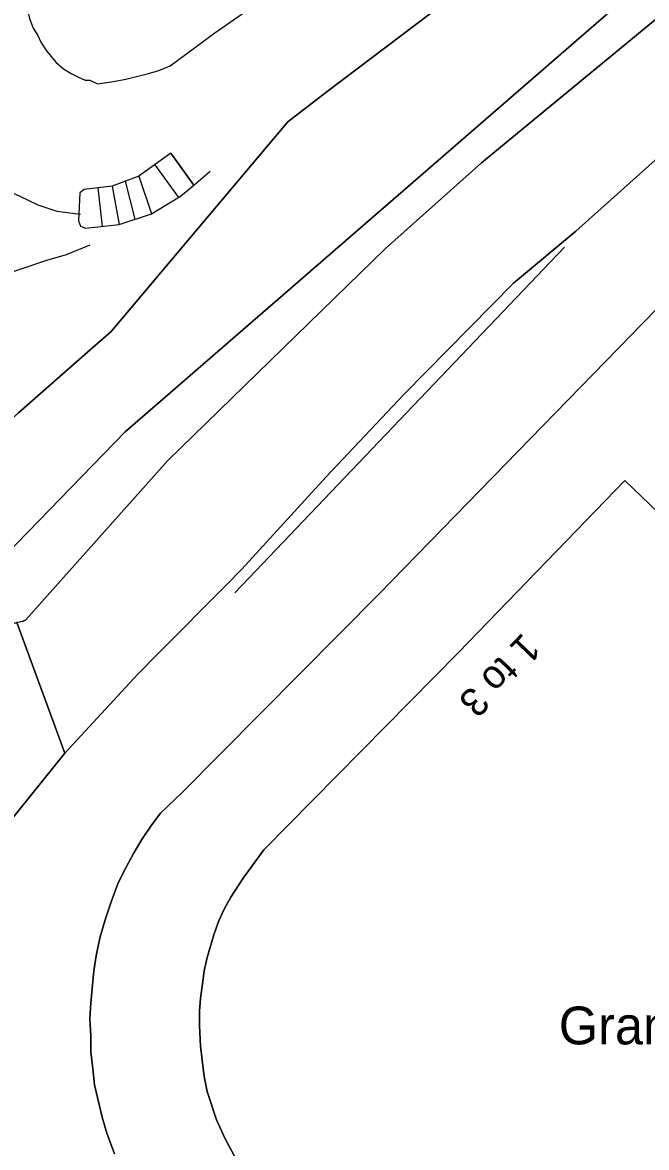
# Model space of a CAD drawing. Extents: x 529240 to 530363, y 179600 to 180767.
# Drawn here: x 530085.5 to 530118.5, y 180396.1 to 180455.7 of the extents above; entities that cross this region are included whole.
import ezdxf

# ---------------------------------------------------------------- set-up
doc = ezdxf.new("R2010")
doc.units = 0
for name, color, linetype in [('Building', 7, 'Continuous'), ('General surface', 7, 'Continuous'), ('Road Or Track', 7, 'Continuous'), ('Roadside', 7, 'Continuous'), ('Unclassified', 7, 'Continuous')]:
    doc.layers.add(name, color=color, linetype=linetype)

msp = doc.modelspace()

# ---------------------------------------------------------------- linework, layer by layer
at = {"layer": 'Building'}
for points in [[(530085.7, 180456.85), (530085.7, 180456.6), (530085.85, 180455.9), (530086.05, 180455.4), (530086.3, 180455), (530086.45, 180454.65), (530086.75, 180454.2), (530087.25, 180453.6), (530087.65, 180453.25), (530088.05, 180453), (530088.45, 180452.8), (530088.8, 180452.65), (530089.05, 180452.65), (530089.45, 180452.45), (530090.2, 180452.55), (530090.95, 180452.7), (530092.15, 180453), (530092.7, 180453.15), (530093.3, 180453.4), (530095.65, 180455.15), (530105.2, 180461.8)], [(530085.85, 180455.9), (530086.05, 180455.4), (530086.3, 180455), (530086.45, 180454.65), (530086.75, 180454.2), (530087.25, 180453.6), (530087.65, 180453.25), (530088.05, 180453), (530088.45, 180452.8), (530088.8, 180452.65), (530089.05, 180452.65), (530089.45, 180452.45), (530090.2, 180452.55), (530090.95, 180452.7), (530092.15, 180453), (530092.7, 180453.15), (530093.3, 180453.4), (530095.65, 180455.15), (530105.2, 180461.8)], [(530119, 180440.5), (530104.35, 180425.45), (530093.9, 180414.9), (530092.8, 180413.85), (530092.3, 180413.2), (530091.8, 180412.45), (530091.35, 180411.7), (530090.95, 180410.95), (530090.55, 180410.15), (530090.15, 180409.1), (530089.85, 180408.2), (530089.6, 180407.3), (530089.4, 180406.4), (530089.25, 180405.5), (530089.1, 180403.8), (530089.05, 180402.95), (530089.1, 180402.05), (530089.1, 180401.2), (530089.2, 180400.3), (530089.3, 180399.45), (530089.7, 180397.75), (530089.95, 180396.9), (530090.35, 180395.8)], [(530119, 180440.5), (530104.35, 180425.45), (530093.9, 180414.9), (530092.8, 180413.85), (530092.3, 180413.2), (530091.8, 180412.45), (530091.35, 180411.7), (530090.95, 180410.95), (530090.55, 180410.15), (530090.15, 180409.1), (530089.85, 180408.2), (530089.6, 180407.3), (530089.4, 180406.4), (530089.25, 180405.5), (530089.1, 180403.8), (530089.05, 180402.95), (530089.1, 180402.05), (530089.1, 180401.2), (530089.2, 180400.3), (530089.3, 180399.45), (530089.7, 180397.75), (530089.95, 180396.9), (530090.35, 180395.8)], [(530155.45, 180405.1), (530126.8, 180433.1), (530121.3, 180427.65), (530117.35, 180431.45), (530108.55, 180422.35), (530098.25, 180411.9), (530097.15, 180410.4), (530096.5, 180409.4), (530096.15, 180408.75), (530095.85, 180408.1), (530095.6, 180407.4), (530095.25, 180406.2), (530095.1, 180405.5), (530095, 180404.8), (530094.9, 180404.05), (530094.85, 180403.35), (530094.85, 180402.6), (530094.9, 180401.5), (530095.1, 180399.9), (530095.25, 180399.1), (530095.75, 180397.6), (530096.2, 180396.6), (530096.9, 180395.3)], [(530096.9, 180395.3), (530096.2, 180396.6), (530095.75, 180397.6), (530095.25, 180399.1), (530095.1, 180399.9), (530094.9, 180401.5), (530094.85, 180402.6), (530094.85, 180403.35), (530094.9, 180404.05), (530095, 180404.8), (530095.1, 180405.5), (530095.25, 180406.2), (530095.6, 180407.4), (530095.85, 180408.1), (530096.15, 180408.75), (530096.5, 180409.4), (530097.15, 180410.4), (530098.25, 180411.9), (530108.55, 180422.35), (530117.35, 180431.45), (530121.3, 180427.65), (530126.8, 180433.1)], [(530096.9, 180395.3), (530096.2, 180396.6), (530095.75, 180397.6), (530095.25, 180399.1), (530095.1, 180399.9), (530094.9, 180401.5), (530094.85, 180402.6), (530094.85, 180403.35), (530094.9, 180404.05), (530095, 180404.8), (530095.1, 180405.5), (530095.25, 180406.2), (530095.6, 180407.4), (530095.85, 180408.1), (530096.15, 180408.75), (530096.5, 180409.4), (530097.15, 180410.4), (530098.25, 180411.9), (530108.55, 180422.35), (530117.35, 180431.45), (530121.3, 180427.65)]]:
    msp.add_lwpolyline(points, dxfattribs=at)
at = {"layer": 'General surface'}
msp.add_lwpolyline([(530094.54, 180447.09), (530093.33, 180448.78), (530091.63, 180447.56), (530090.23, 180447.03), (530088.74, 180446.86), (530088.51, 180446.68), (530088.44, 180445.19), (530088.55, 180444.92), (530088.81, 180444.8), (530090.6, 180445), (530092.3, 180445.57), (530093.84, 180446.5)], close=True, dxfattribs=at)
for points in [[(530093.33, 180448.78), (530094.54, 180447.09)], [(530092.48, 180448.17), (530093.73, 180446.43)], [(530091.45, 180445.28), (530090.93, 180447.3)], [(530091.63, 180447.56), (530092.3, 180445.57)], [(530089.71, 180444.9), (530089.48, 180446.94)], [(530090.23, 180447.03), (530090.6, 180445)]]:
    msp.add_lwpolyline(points, dxfattribs=at)
at = {"layer": 'Road Or Track'}
for points in [[(530083.71, 180426.65), (530083.76, 180426.7), (530083.81, 180426.75), (530083.86, 180426.8), (530083.91, 180426.84), (530083.96, 180426.89), (530084.02, 180426.93), (530090.91, 180434.02), (530103.62, 180445.06), (530118.34, 180457.85), (530120.09, 180459.31), (530146.35, 180481.2), (530151.51, 180485.78), (530157.33, 180491.64), (530165.15, 180500), (530166.31, 180501.24)], [(530168.55, 180499.29), (530168.43, 180498.73), (530158.53, 180489.31), (530154.01, 180485.26), (530126.57, 180462.42), (530126.03, 180462.58), (530125.18, 180461.87), (530125.27, 180461.71), (530125.12, 180461.17), (530121.3, 180457.85), (530119.86, 180456.6), (530109.76, 180448.27), (530104.69, 180443.73), (530093.17, 180432.51), (530088.24, 180426.97), (530085.64, 180424.05), (530085.52, 180424), (530085.46, 180423.98), (530085.39, 180423.96), (530085.32, 180423.95), (530085.25, 180423.94), (530085.18, 180423.93)], [(530143.57, 180487.15), (530143.24, 180486.84), (530129.75, 180474.3), (530127.05, 180471.9), (530126.1, 180471.25), (530121.6, 180467.65), (530119.3, 180465.8), (530117.65, 180464.55), (530115.95, 180463.2), (530112.95, 180460.85), (530110.95, 180459.3), (530107.15, 180456.25), (530101.6, 180452.05)], [(530107.15, 180456.25), (530101.6, 180452.05), (530099.52, 180450.44), (530090.17, 180439.34), (530089.07, 180438.37), (530085.28, 180435.03), (530083.69, 180433.62), (530083.1, 180433.59), (530083.71, 180426.65), (530083.76, 180426.7), (530083.81, 180426.75), (530083.86, 180426.8), (530083.91, 180426.84), (530083.96, 180426.89), (530084.02, 180426.93), (530090.91, 180434.02), (530103.62, 180445.06), (530118.34, 180457.85)], [(530119.86, 180456.6), (530109.76, 180448.27), (530104.69, 180443.73), (530093.17, 180432.51), (530088.24, 180426.97), (530085.64, 180424.05), (530085.52, 180424), (530085.46, 180423.98), (530085.39, 180423.96), (530085.32, 180423.95), (530085.25, 180423.94), (530085.18, 180423.93), (530087.72, 180417.02), (530091.59, 180421.2), (530092.65, 180422.27), (530096.27, 180425.93), (530097.08, 180426.75), (530101.55, 180431.65), (530105.65, 180436), (530111.45, 180441.9), (530114.75, 180444.65), (530118.95, 180448.4)], [(530101.6, 180452.05), (530099.52, 180450.44), (530090.17, 180439.34), (530089.07, 180438.37), (530085.28, 180435.03), (530083.69, 180433.62), (530083.1, 180433.59)], [(530123.65, 180452.3), (530118.95, 180448.4), (530114.75, 180444.65), (530111.45, 180441.9), (530105.65, 180436), (530101.55, 180431.65), (530097.08, 180426.75), (530096.27, 180425.93), (530092.65, 180422.27), (530091.59, 180421.2), (530087.72, 180417.02)], [(530087.72, 180417.02), (530084.15, 180412.58), (530080.91, 180407.89), (530076.79, 180400.63), (530076, 180398.36), (530075.64, 180395.99)]]:
    msp.add_lwpolyline(points, dxfattribs=at)
msp.add_lwpolyline([(530075.45, 180420.08), (530075.54, 180419.53), (530068.51, 180404.42), (530066.03, 180399.09), (530064.72, 180396.29), (530075.64, 180395.99), (530076, 180398.36), (530076.79, 180400.63), (530080.91, 180407.89), (530084.15, 180412.58), (530087.72, 180417.02), (530085.18, 180423.93)], close=True, dxfattribs=at)
at = {"layer": 'Roadside'}
for points in [[(530152.75, 180475.95), (530149.65, 180473.2), (530144.6, 180469), (530140.6, 180465.95), (530132.05, 180458.95), (530129.35, 180456.85), (530124.45, 180452.95), (530123.65, 180452.3), (530118.95, 180448.4), (530114.75, 180444.65), (530111.45, 180441.9), (530105.65, 180436), (530101.55, 180431.65), (530097.08, 180426.75), (530096.27, 180425.93), (530092.65, 180422.27), (530091.59, 180421.2), (530087.72, 180417.02), (530084.15, 180412.58), (530080.91, 180407.89), (530076.79, 180400.63), (530076, 180398.36), (530075.64, 180395.99)], [(530085.85, 180455.9), (530086.05, 180455.4), (530086.3, 180455), (530086.45, 180454.65), (530086.75, 180454.2), (530087.25, 180453.6), (530087.65, 180453.25), (530088.05, 180453), (530088.45, 180452.8), (530088.8, 180452.65), (530089.05, 180452.65), (530089.45, 180452.45), (530090.2, 180452.55), (530090.95, 180452.7), (530092.15, 180453), (530092.7, 180453.15), (530093.3, 180453.4), (530095.65, 180455.15), (530105.2, 180461.8)], [(530118.34, 180457.85), (530103.62, 180445.06), (530090.91, 180434.02), (530084.02, 180426.93)], [(530078.95, 180456.89), (530081.21, 180444.77), (530081.52, 180441.99), (530082.06, 180437.03), (530082.35, 180434.44), (530082.59, 180433.9), (530083.1, 180433.59), (530083.69, 180433.62), (530085.28, 180435.03), (530089.07, 180438.37), (530090.17, 180439.34), (530099.52, 180450.44), (530101.6, 180452.05), (530107.15, 180456.25)], [(530085.46, 180423.98), (530085.52, 180424), (530085.64, 180424.05), (530088.24, 180426.97), (530093.17, 180432.51), (530104.69, 180443.73), (530109.76, 180448.27), (530119.86, 180456.6)], [(530090.35, 180395.8), (530089.95, 180396.9), (530089.7, 180397.75), (530089.3, 180399.45), (530089.2, 180400.3), (530089.1, 180401.2), (530089.1, 180402.05), (530089.05, 180402.95), (530089.1, 180403.8), (530089.25, 180405.5), (530089.4, 180406.4), (530089.6, 180407.3), (530089.85, 180408.2), (530090.15, 180409.1), (530090.55, 180410.15), (530090.95, 180410.95), (530091.35, 180411.7), (530091.8, 180412.45), (530092.3, 180413.2), (530092.8, 180413.85), (530093.9, 180414.9), (530104.35, 180425.45), (530119, 180440.5)]]:
    msp.add_lwpolyline(points, dxfattribs=at)
msp.add_lwpolyline([(530094.54, 180447.09), (530093.33, 180448.78), (530091.63, 180447.56), (530090.23, 180447.03), (530088.74, 180446.86), (530088.51, 180446.68), (530088.44, 180445.19), (530088.55, 180444.92), (530088.81, 180444.8), (530090.6, 180445), (530092.3, 180445.57), (530093.84, 180446.5)], close=True, dxfattribs=at)
at = {"layer": 'Unclassified'}
for points in [[(530082.75, 180448.55), (530083.3, 180448.05), (530083.85, 180447.4), (530084.25, 180447.15), (530084.8, 180446.75), (530085.35, 180446.5), (530086.3, 180446.05), (530087.3, 180445.7), (530088.55, 180445.55)], [(530093.33, 180448.78), (530091.63, 180447.56), (530090.23, 180447.03), (530088.74, 180446.86), (530088.51, 180446.68), (530088.44, 180445.19), (530088.55, 180444.92), (530088.81, 180444.8), (530090.6, 180445), (530092.3, 180445.57), (530093.84, 180446.5), (530094.54, 180447.09)], [(530094.54, 180447.09), (530095.41, 180447.82)], [(530089.05, 180443.9), (530087.8, 180443.4), (530086.75, 180443.1), (530084.4, 180442.3), (530082.15, 180441.45), (530080.15, 180441), (530074.45, 180439.95), (530070.2, 180439.15), (530064.5, 180438.15), (530064.45, 180436.6), (530064.35, 180435.05), (530064.1, 180434.1), (530063.7, 180432.3)], [(530114.15, 180443.8), (530096.71, 180425.51)], [(530085.18, 180423.93), (530087.72, 180417.02)]]:
    msp.add_lwpolyline(points, dxfattribs=at)

# ---------------------------------------------------------------- texts
msp.add_text('1 to 3', height=1.5, rotation=226, dxfattribs=at).set_placement((530111.95, 180423.45))
msp.add_text('Grand Buildings', height=2, dxfattribs=at).set_placement((530113.85, 180401.6))

doc.saveas('drawing.dxf')
